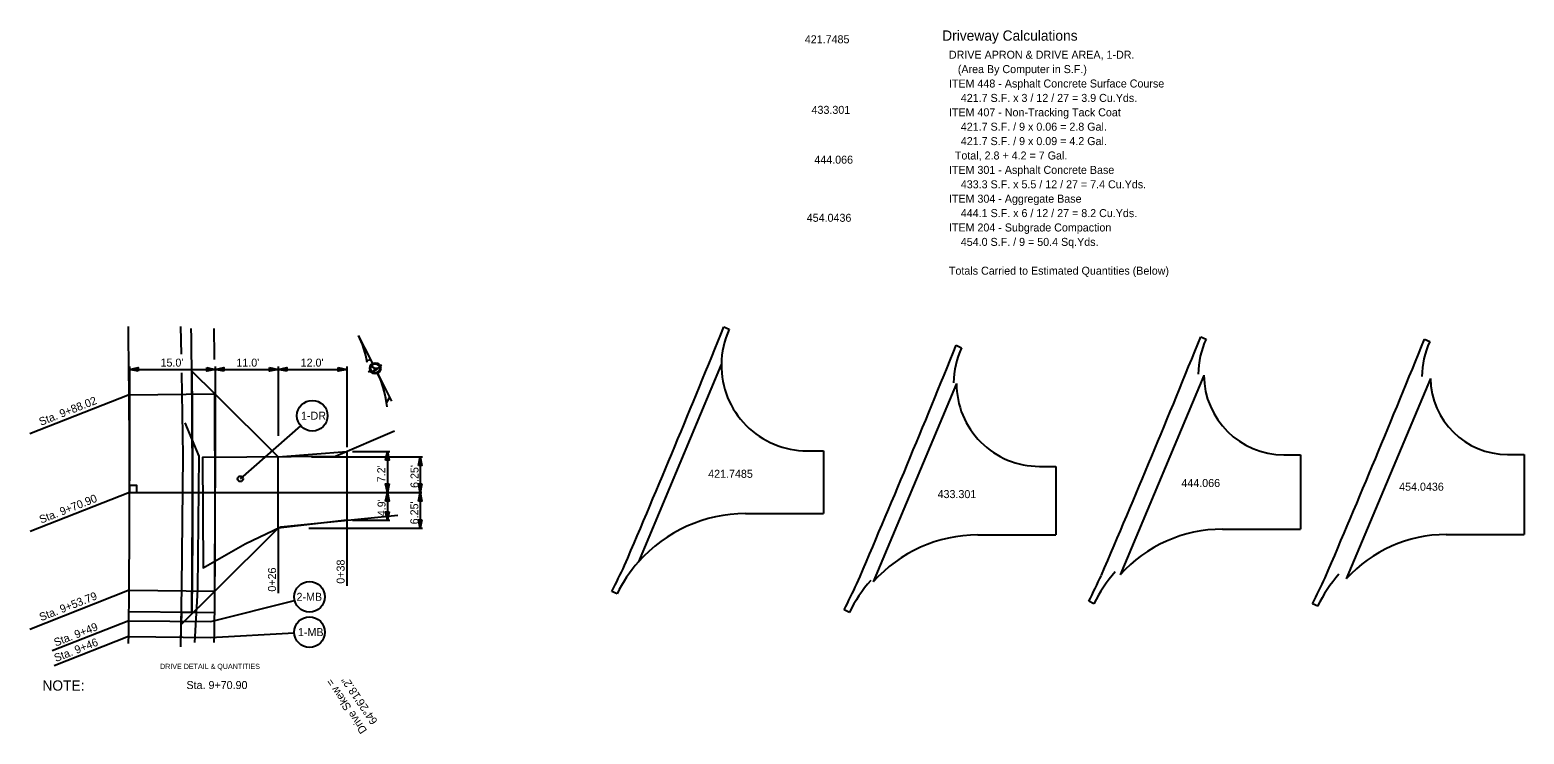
# Model space of a CAD drawing. Extents: x -736 to 9385, y -1086 to 4832.
# Drawn here: x 214 to 475.4, y 229.4 to 352.6 of the extents above; entities that cross this region are included whole.
import ezdxf

# ---------------------------------------------------------------- set-up
doc = ezdxf.new("R2010")
doc.units = 0
for name, color, linetype in [('BR_P_Gen_Joint_Filler', 7, 'Continuous'), ('DR_P_Cells', 7, 'Continuous'), ('DT_P_Slope_Break_Line', 7, 'Continuous'), ('DT_X_Contour_Major', 7, 'Continuous'), ('DT_X_Contour_Text', 7, 'Continuous'), ('DT_X_Island', 7, 'Continuous'), ('DT_X_Terrain_Boundary', 7, 'Continuous'), ('DT_X_Triangles', 7, 'Continuous'), ('GK_Drainage_Nodes', 7, 'Continuous'), ('GT_Project_Soil_Boring', 7, 'Continuous'), ('PV_P_Drive', 7, 'Continuous'), ('PV_P_Field_Drive', 7, 'Continuous'), ('PV_X_Shoulder_Aggregate', 7, 'Continuous'), ('SC_Scratch1', 7, 'Continuous'), ('UT_X_Telecom', 7, 'Continuous')]:
    doc.layers.add(name, color=color, linetype=linetype)

msp = doc.modelspace()

# ---------------------------------------------------------------- linework, layer by layer
at = {"layer": 'BR_P_Gen_Joint_Filler'}
for p, q in [((274.01, 294.25), (271.54, 299.13)), ((272.99, 294.76), (273.68, 294.91)), ((273.28, 292.8), (273.59, 292.95)), ((275.31, 293.82), (275.62, 293.98)), ((277.36, 287.65), (274.89, 292.53)), ((277.02, 288.32), (276.45, 287.41))]:
    msp.add_line(p, q, dxfattribs=at)
for points in [[(272.98, 294.76), (272.99, 294.76), (273.68, 294.91), (271.54, 299.13)], [(276.45, 287.41), (277.02, 288.32), (274.89, 292.53)]]:
    msp.add_lwpolyline(points, dxfattribs=at)
for radius in [0.965, 0.794]:
    msp.add_circle((274.45, 293.39), radius, dxfattribs=at)
for centre, radius, start, end in [((256.35, 291.7), 16.91, 9.2887, 26.0681), ((256.35, 291.7), 16.91, 10.4488, 26.0681), ((274.64, 294.51), 1.09, 226.0309, 296.2444), ((275.06, 294.7), 1.54, 219.7291, 254.1876), ((273.67, 294.82), 1.94, 279.3608, 318.3594), ((273.25, 295.24), 2.45, 287.6011, 304.7469), ((259.69, 285.09), 16.91, 5.3788, 26.0681), ((259.69, 285.09), 16.91, 7.8671, 26.0681)]:
    msp.add_arc(centre, radius, start, end, dxfattribs=at)
at = {"layer": 'DT_P_Slope_Break_Line'}
msp.add_line((231.48, 271.66), (282.58, 271.66), dxfattribs=at)
at = {"layer": 'DT_X_Contour_Major'}
msp.add_circle((250.86, 274.05), 0.48, dxfattribs=at)
at = {"layer": 'DT_X_Contour_Text'}
for p, q in [((335.45, 300.65), (336.37, 300.22)), ((418.87, 298.93), (419.8, 298.5)), ((458, 298.5), (458.93, 298.07)), ((376.09, 297.42), (377.01, 297)), ((231.47, 293.73), (231.47, 273.68)), ((231.47, 293.21), (246.47, 293.21)), ((246.47, 293.73), (246.47, 272.45)), ((246.47, 293.21), (257.47, 293.21)), ((257.47, 293.73), (257.47, 281.57)), ((257.47, 293.21), (269.47, 293.21)), ((269.47, 293.73), (269.47, 279.6)), ((335, 294.09), (320.5, 259.5)), ((376.14, 290.76), (361.56, 256)), ((419.42, 292.16), (404.78, 257.24)), ((459.06, 291.63), (444.33, 256.53)), ((231.41, 288.77), (214.04, 281.94)), ((231.41, 288.77), (246.41, 288.9)), ((263.32, 277.9), (282.73, 277.9)), ((270.49, 278.82), (277.03, 278.82)), ((276.58, 278.82), (276.58, 271.66)), ((282.34, 277.9), (282.34, 271.66)), ((231.48, 271.66), (214.12, 264.82)), ((276.58, 271.66), (276.58, 266.8)), ((282.34, 271.66), (282.34, 265.41)), ((269.48, 266.8), (269.48, 255.34)), ((270.49, 266.8), (277.03, 266.8)), ((257.47, 265.41), (257.47, 254.04)), ((262.87, 265.41), (282.73, 265.41)), ((231.41, 254.54), (214.04, 247.71)), ((231.41, 254.54), (246.41, 254.41)), ((316.77, 253.9), (315.87, 254.34)), ((357.4, 250.68), (356.5, 251.11)), ((400.19, 252.18), (399.29, 252.62)), ((439.32, 251.75), (438.42, 252.19)), ((231.35, 249.22), (217.95, 243.94)), ((231.35, 249.22), (245.68, 249.06)), ((231.32, 246.45), (218.27, 241.31)), ((231.32, 246.45), (245.63, 246.26))]:
    msp.add_line(p, q, dxfattribs=at)
for points in [[(232.97, 292.91), (231.47, 293.21), (232.97, 293.51)], [(244.98, 293.51), (246.47, 293.21), (244.98, 292.91)], [(247.97, 292.91), (246.47, 293.21), (247.97, 293.51)], [(255.98, 293.51), (257.47, 293.21), (255.98, 292.91)], [(258.97, 292.91), (257.47, 293.21), (258.97, 293.51)], [(267.98, 293.51), (269.47, 293.21), (267.98, 292.91)], [(276.28, 277.32), (276.58, 278.82), (276.88, 277.32)], [(282.04, 276.41), (282.34, 277.9), (282.63, 276.41)], [(231.48, 271.66), (232.73, 271.66), (232.73, 272.91), (231.48, 272.91)], [(276.88, 273.15), (276.58, 271.66), (276.28, 273.15)], [(282.63, 273.15), (282.34, 271.66), (282.04, 273.15)], [(276.28, 270.16), (276.58, 271.66), (276.88, 270.16)], [(282.04, 270.16), (282.34, 271.66), (282.63, 270.16)], [(276.88, 268.29), (276.58, 266.8), (276.28, 268.29)], [(282.63, 266.9), (282.34, 265.41), (282.04, 266.9)]]:
    msp.add_lwpolyline(points, close=True, dxfattribs=at)
for centre, radius, start, end in [((-1698.28, 1122.3), 2193.43, 336.81899, 338.00069), ((350, 293.96), 15, 155.307, 179.5107), ((-1614.85, 1120.58), 2193.43, 336.81899, 338.00069), ((433.42, 292.24), 15, 155.307, 179.5107), ((-1575.72, 1120.15), 2193.43, 336.81899, 338.00069), ((472.55, 291.81), 15, 155.307, 179.5107), ((-1657.64, 1119.07), 2193.43, 336.81899, 338.00069), ((390.64, 290.73), 15, 155.307, 179.5107), ((-1718.36, 1244.99), 2262.63, 334.03433, 334.16216), ((339.24, 242.96), 25, 138.579, 154.0343), ((379.88, 239.73), 25, 138.579, 154.0343), ((-1634.94, 1243.27), 2262.63, 334.03433, 334.16216), ((422.66, 241.24), 25, 138.579, 154.0343), ((-1595.81, 1242.84), 2262.63, 334.03433, 334.16216), ((461.79, 240.81), 25, 138.579, 154.0343), ((-1677.73, 1241.77), 2262.63, 334.03433, 334.16216)]:
    msp.add_arc(centre, radius, start, end, dxfattribs=at)
at = {"layer": 'DT_X_Island'}
for p, q in [((250.86, 274.05), (261.44, 283.34)), ((245.68, 249.06), (260.36, 252.75)), ((245.63, 246.26), (260.29, 247.07))]:
    msp.add_line(p, q, dxfattribs=at)
msp.add_lwpolyline([(242.48, 275.51), (242.47, 263.89), (242.43, 257.25), (242.37, 250.64), (240.54, 250.66), (240.51, 248.55), (246.41, 254.41), (246.48, 270.99), (246.41, 286.84), (246.41, 288.9), (242.37, 292.91), (242.43, 285.95)], close=True, dxfattribs=at)
at = {"layer": 'DT_X_Terrain_Boundary'}
for centre in [(263.45, 285.1), (262.96, 253.4), (262.96, 247.22)]:
    msp.add_circle(centre, 2.68, dxfattribs=at)
at = {"layer": 'GK_Drainage_Nodes'}
for p, q in [((242.37, 292.91), (246.41, 288.9)), ((246.41, 288.9), (257.47, 277.9)), ((257.47, 277.9), (269.47, 278.82)), ((269.47, 278.82), (269.48, 266.8)), ((350, 278.96), (352.88, 278.96)), ((352.88, 278.96), (352.88, 267.96)), ((433.42, 278.24), (436.3, 278.24)), ((436.3, 278.24), (436.3, 265.24)), ((472.55, 278.31), (475.43, 278.31)), ((475.43, 278.31), (475.43, 264.31)), ((390.64, 276.23), (393.52, 276.23)), ((393.52, 276.23), (393.52, 264.23)), ((269.48, 266.8), (257.47, 265.41)), ((339.24, 267.96), (352.88, 267.96)), ((246.41, 254.41), (257.47, 265.41)), ((379.88, 264.23), (393.52, 264.23)), ((422.66, 265.24), (436.3, 265.24)), ((461.79, 264.31), (475.43, 264.31)), ((240.51, 248.55), (246.41, 254.41))]:
    msp.add_line(p, q, dxfattribs=at)
for centre, radius, start, end in [((350, 293.96), 15, 179.5107, 270), ((390.64, 290.73), 14.5, 179.8963, 270), ((433.42, 292.24), 14, 180.3027, 270), ((472.55, 291.81), 13.5, 180.7317, 270), ((-1752.93, 271.66), 2010.41, 359.82195, 0.17805), ((339.24, 242.96), 25, 90, 138.579), ((379.88, 239.73), 24.5, 90, 138.3877), ((422.66, 241.24), 24, 90, 138.1905), ((461.79, 240.81), 23.5, 90, 137.9869)]:
    msp.add_arc(centre, radius, start, end, dxfattribs=at)
at = {"layer": 'GT_Project_Soil_Boring'}
msp.add_lwpolyline([(242.9, 245.38), (243.41, 254.69), (243.67, 278.03), (241.22, 283.86)], dxfattribs=at)
at = {"layer": 'PV_P_Drive'}
for p, q in [((242.37, 250.64), (231.37, 250.76)), ((240.46, 244.67), (240.54, 250.66))]:
    msp.add_line(p, q, dxfattribs=at)
msp.add_arc((-1752.93, 271.66), 1995.41, 359.39651, 0.82423, dxfattribs=at)
at = {"layer": 'PV_P_Field_Drive'}
msp.add_arc((-1752.93, 271.66), 1984.41, 359.23634, 0.83903, dxfattribs=at)
at = {"layer": 'PV_X_Shoulder_Aggregate'}
msp.add_line((240.55, 295.88), (240.46, 300.72), dxfattribs=at)
msp.add_lwpolyline([(240.46, 245.03), (240.6, 255.09), (240.88, 278.16), (240.61, 292.63)], dxfattribs=at)
at = {"layer": 'SC_Scratch1'}
msp.add_line((246.37, 250.6), (242.37, 250.64), dxfattribs=at)
for start, end in [(0.66623, 0.82269), (359.24711, 0.49414)]:
    msp.add_arc((-1752.93, 271.66), 1999.41, start, end, dxfattribs=at)
at = {"layer": 'UT_X_Telecom'}
msp.add_lwpolyline([(277.85, 282.4), (267.49, 277.97), (244.22, 277.81), (244.34, 258.49), (251.72, 262.69), (257.94, 265.63), (278.43, 267.7)], dxfattribs=at)

# ---------------------------------------------------------------- texts
at = {"layer": 'DR_P_Cells'}
for s, p in [('Drive Skew =', (273.09, 230.02)), ('64°26\'18.2"', (274.95, 231.64))]:
    msp.add_text(s, height=1.4, rotation=123.9452, dxfattribs=at).set_placement(p)
at = {"layer": 'DT_X_Contour_Major'}
for s, height, p in [('Driveway Calculations', 1.8, (373.64, 350.73)), ('DRIVE DETAIL & QUANTITIES', 0.9, (236.82, 240.78)), ('NOTE:', 1.8, (216.24, 236.98))]:
    msp.add_text(s, height=height, dxfattribs=at).set_placement(p)
at = {"layer": 'DT_X_Contour_Text'}
for s, p in [('421.7485', (349.6, 350.28)), ('433.301', (350.78, 337.93)), ('444.066', (351.27, 329.21)), ('454.0436', (349.94, 319.04)), ("15.0'", (236.9, 293.69)), ("11.0'", (250.17, 293.69)), ("12.0'", (261.41, 293.69)), ('421.7485', (332.7, 274.23)), ('433.301', (372.83, 270.68)), ('444.066', (415.48, 272.62)), ('454.0436', (453.57, 271.97)), ('Sta. 9+70.90', (241.44, 237.26))]:
    msp.add_text(s, height=1.4, dxfattribs=at).set_placement(p)
for s, rotation, p in [('Sta. 9+88.02', 21.4812, (215.97, 283.32)), ("7.2'", 90, (276.21, 273.45)), ("6.25'", 90, (282.03, 272.46)), ('Sta. 9+70.90', 21.4812, (216.01, 266.2)), ("4.9'", 90, (276.26, 267.51)), ("6.25'", 90, (282, 266.09)), ('0+38', 90, (269.1, 255.7)), ('0+26', 90, (257.1, 254.31)), ('Sta. 9+53.79', 21.4812, (216.02, 249.12))]:
    msp.add_text(s, height=1.4, rotation=rotation, dxfattribs=at).set_placement(p)
at = {"layer": 'DT_X_Terrain_Boundary'}
for s, p in [('DRIVE APRON & DRIVE AREA, 1-DR.', (374.81, 347.58)), ('   (Area By Computer in S.F.)', (374.81, 345.06)), ('ITEM 448 - Asphalt Concrete Surface Course', (374.81, 342.54)), ('    421.7 S.F. x 3 / 12 / 27 = 3.9 Cu.Yds.', (374.81, 340.02)), ('ITEM 407 - Non-Tracking Tack Coat', (374.81, 337.5)), ('    421.7 S.F. / 9 x 0.06 = 2.8 Gal.', (374.81, 334.98)), ('    421.7 S.F. / 9 x 0.09 = 4.2 Gal.', (374.81, 332.46)), ('  Total, 2.8 + 4.2 = 7 Gal.', (374.81, 329.94)), ('ITEM 301 - Asphalt Concrete Base', (374.81, 327.42)), ('    433.3 S.F. x 5.5 / 12 / 27 = 7.4 Cu.Yds.', (374.81, 324.9)), ('ITEM 304 - Aggregate Base', (374.81, 322.38)), ('    444.1 S.F. x 6 / 12 / 27 = 8.2 Cu.Yds.', (374.81, 319.86)), ('ITEM 204 - Subgrade Compaction', (374.81, 317.34)), ('    454.0 S.F. / 9 = 50.4 Sq.Yds.', (374.81, 314.82)), ('Totals Carried to Estimated Quantities (Below)', (374.81, 309.78)), ('1-DR', (261.48, 284.4)), ('2-MB', (260.69, 252.7)), ('1-MB', (260.94, 246.52))]:
    msp.add_text(s, height=1.4, dxfattribs=at).set_placement(p)
at = {"layer": 'DT_X_Triangles'}
for s, p in [('Sta. 9+49', (218.57, 244.68)), ('Sta. 9+46', (218.61, 241.98))]:
    msp.add_text(s, height=1.4, rotation=21.4812, dxfattribs=at).set_placement(p)

doc.saveas('drawing.dxf')
